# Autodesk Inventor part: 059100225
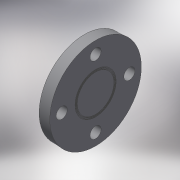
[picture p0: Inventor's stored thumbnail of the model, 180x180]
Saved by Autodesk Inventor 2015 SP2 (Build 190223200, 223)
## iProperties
Created: 2017-10
Part Number: 059100225
Material: Generic
Description: PLASSON BLANK FLANGE PVC 225
Document SubType Name: Modeling
Designer: KIM
Density: 1 g/cm^3
Appearance: Default
Author: KIM
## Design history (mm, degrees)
derived "059100.ipt"
feature "Solid1::059100.ipt"
tag "TaggingFeature1"
body "Solid1"
other parameters: "d0" = 32, "d3" = 336.6, "d12" = 45 deg, "d14" = 22, "d15" = 148.5, "d16" = 32, "d17" = 0, "d19" = 360 deg, "d21" = 1.7, "d22" = 1.7, "d23" = 1.7, "d24" = 1.7, "d25" = 1.7, "d26" = 0.68, "d27" = 0, "H_" = 32, "Dp_" = 297, "S_" = 22
